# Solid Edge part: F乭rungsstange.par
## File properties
Dokumentum tartalom típus: 0
Last saved by: bmolnar
Revision: 76
Sűrűség: 0,000 kg/m^3
Pontosság: 0,990
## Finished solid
Body 1: solid body, 8 faces, 7 edges, 7 vertices.
  Faces by surface: cone 4, cylinder 2, plane 2
  Edges by curve: circle 7
Bounding box of the edges (mm): 8.000 x 8.000 x 52.000, from (-4, -4, -26) to (4, 4, 26).
Cylindrical faces by radius (mm): R2.067 x1, R4 x1
Conical faces (half-angle, radius in mm at the cone's reference point): 45 deg R2.217 x1, 45 deg R3.5 x1, 45 deg R3.9 x1, 59 deg R1.0335 x1
Planar faces by outward normal: +z 1, -z 1
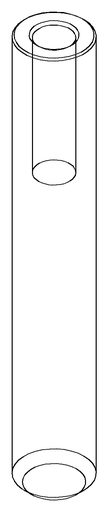
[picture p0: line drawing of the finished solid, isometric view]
